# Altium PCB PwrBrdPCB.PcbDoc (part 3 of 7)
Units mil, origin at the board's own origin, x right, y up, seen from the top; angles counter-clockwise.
Board outline 8000 x 5500 mil, 4 copper layers (Top Layer, Internal 1, Internal 2, Bottom Layer), stack 61.834 mil thick; 682 components, 380 nets, 1899 pads, 766 vias.
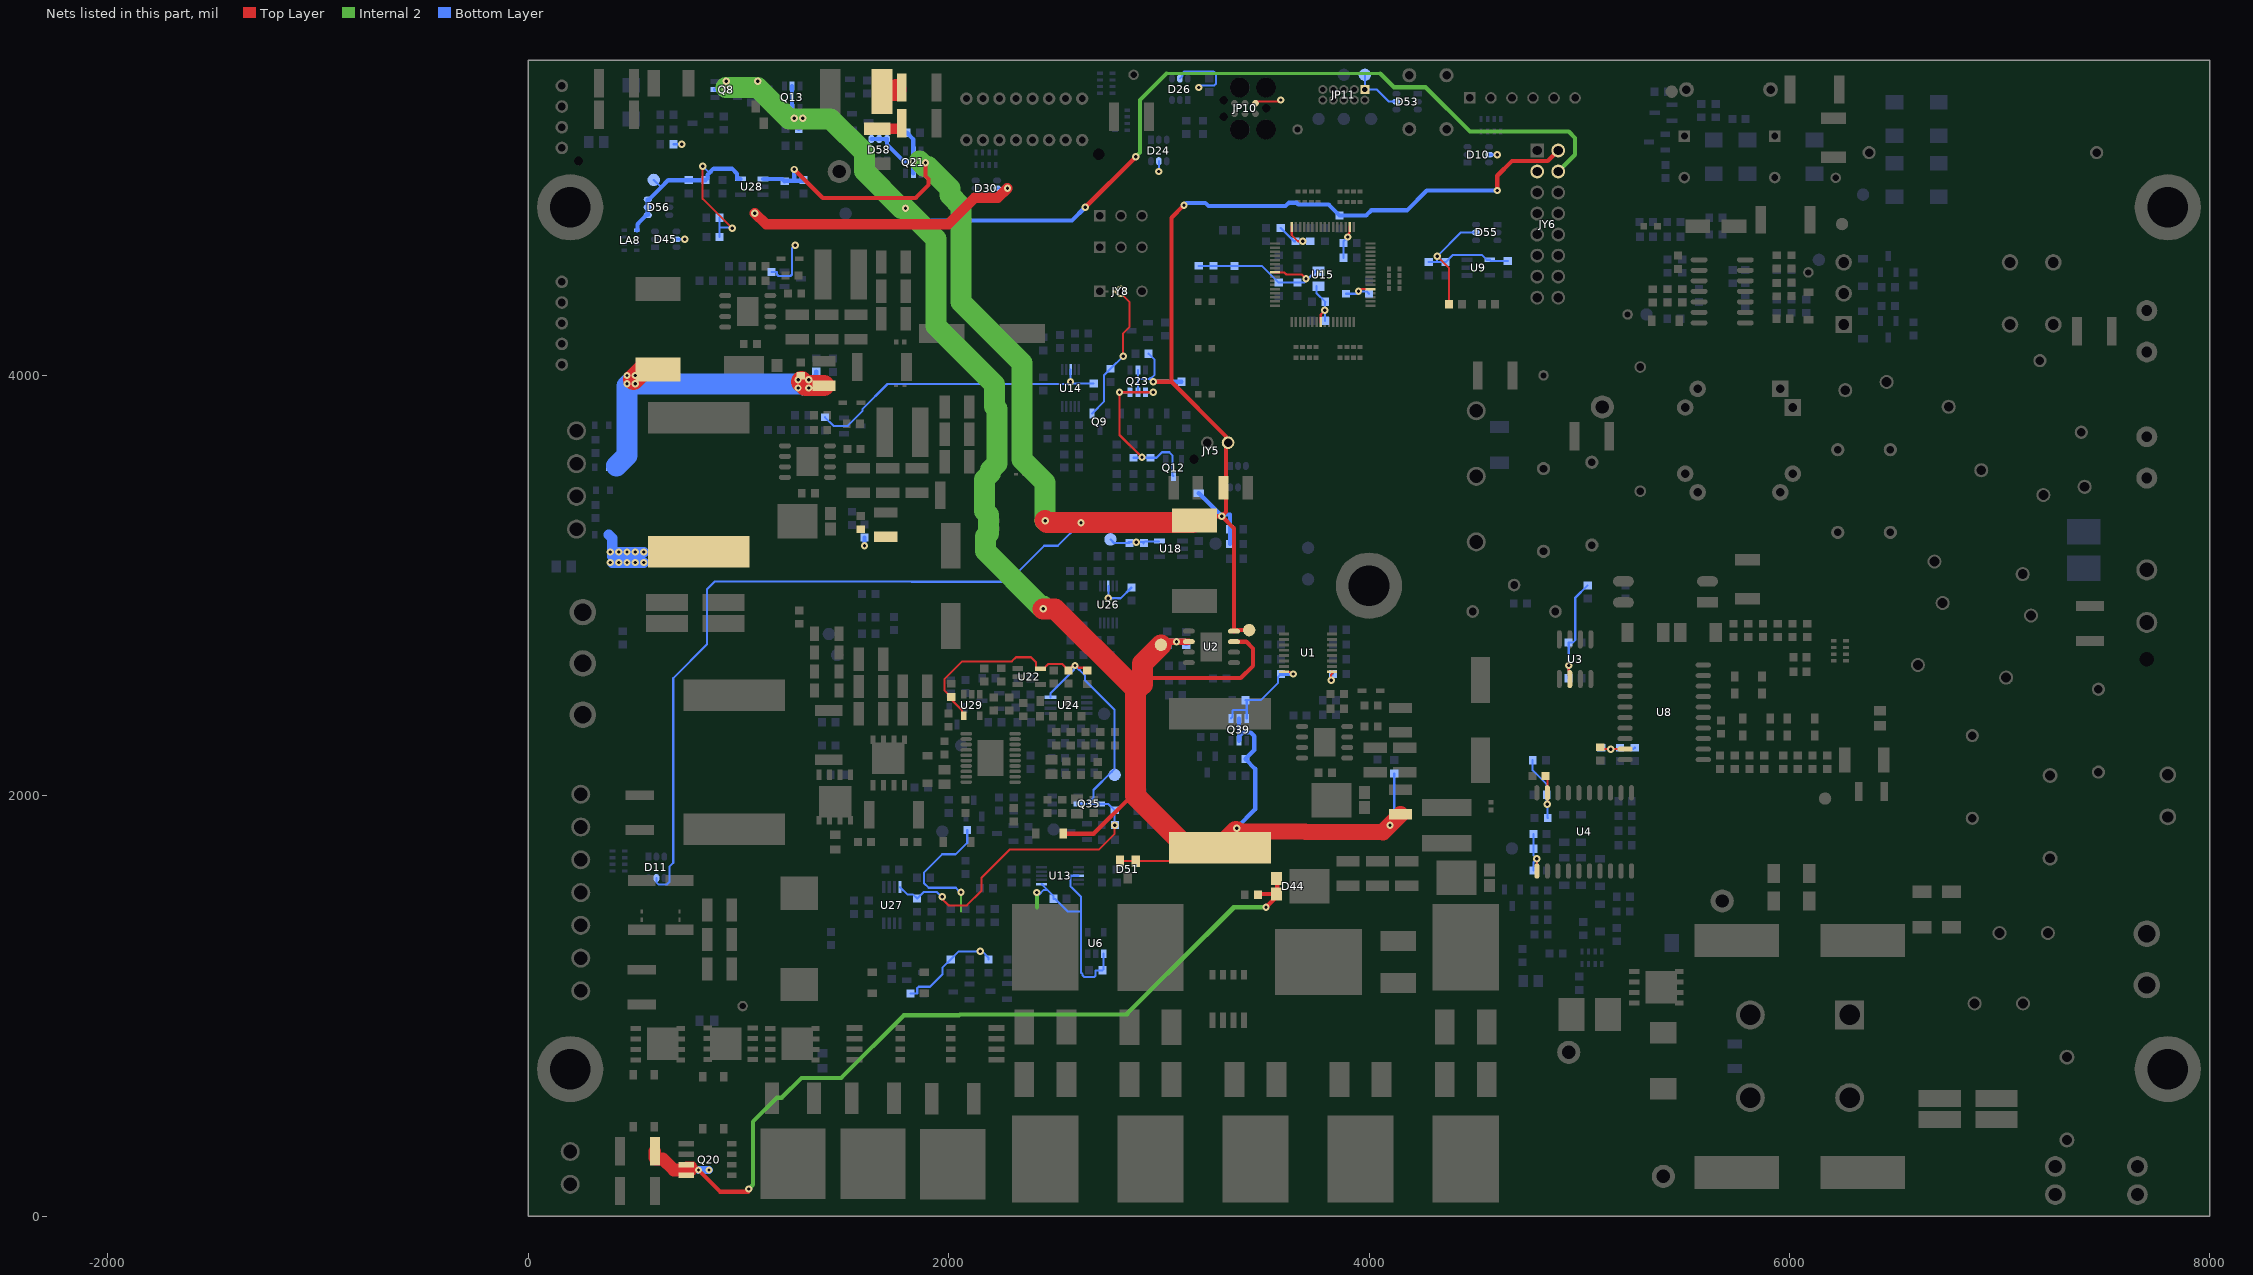
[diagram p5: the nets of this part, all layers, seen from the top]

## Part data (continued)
D4 D5 D6 D7 D19 D20 D21 D22 D27 D28 D32 D33 D34 D35 D36 D37 D47: library part DIO-00004, "Diode Standard 100V 150mA Surface Mount SOD-123", manufacturer="Micro Commercial Co", manufacturer_pn=1N4148W-TP, Supplier Part Number 1=1N4148WTPMSCT-ND
D8: library part DIO-00038, "TVS DIODE 26VWM 42.1VC SMD", manufacturer="Bourns Inc.", manufacturer_pn=5.0SMDJ26CA-H, Supplier Part Number 1=5.0SMDJ26CA-HCT-ND
D10 D24 D26 D30 D45 D53 D55 D56: library part DIO-00013, "TVS DIODE 3.3VWM 6VC SOT26", manufacturer="Diodes Incorporated", manufacturer_pn=D5V0P4UR6SO-7, Supplier Part Number 1=D5V0P4UR6SO-7DICT-ND
D11 D52 D58: library part DIO-00000, "TVS DIODE 6TSOP", manufacturer="Nexperia USA Inc.", manufacturer_pn=PRTR5V0U4D,125, Supplier Part Number 1=1727-3890-1-ND
D12 D41 D42 D43 D44: library part DIO-00037, "Diode Schottky 60V 20A Surface Mount TO-277A (SMPC)", manufacturer="Taiwan Semiconductor Corporation", manufacturer_pn="TSP20U60S S1G", Supplier Part Number 1="TSP20U60S S1GCT-ND"
D13: library part DIO-00010, "Zener Diode 10V 1W ±5% Surface Mount SMA", manufacturer="Diodes Incorporated", manufacturer_pn=SMAZ10-13-F, Supplier Part Number 1=SMAZ10-FDICT-ND
D14 D15 D25 D38 D39: library part DIO-00009, "Diode Standard 1000V (1kV) 1A Surface Mount SMA (DO-214AC)", manufacturer="Fairchild Semiconductor", manufacturer_pn=S1M, Supplier Part Number 1=S1MFSCT-ND
D16 D40: library part DIO-00017, "Zener Diode 8.2V 1W ±5% Surface Mount SMA", manufacturer="Diodes Incorporated", manufacturer_pn=SMAZ8V2-13-F, Supplier Part Number 1=SMAZ8V2-FDICT-ND
D17: library part DIO-00011, "Diode Standard 4000V (4kV) 250mA Through Hole DO-204AL (DO-41)", manufacturer="Vishay Semiconductor Diodes Division", manufacturer_pn=GP02-40-E3/54, Supplier Part Number 1=GP02-40-E3/54GICT-ND
D23 D49 D50: library part DIO-00042, "Zener Diode 5.6V 200mW ±2% Surface Mount SOD-323F", manufacturer="ON Semiconductor", manufacturer_pn=MM3Z5V6B, Supplier Part Number 1=MM3Z5V6BCT-ND
D29: library part DIO-00018, "TVS DIODE 24VWM 38.9VC SMA", manufacturer="Diodes Incorporated", manufacturer_pn=SMAJ24A-13-F, Supplier Part Number 1=SMAJ24A-FDICT-ND
D31: library part LED-00007, "Green 571nm LED Indication - Discrete 2V 0603 (1608 Metric) 35mcd clear", manufacturer="Lite-On Inc.", manufacturer_pn=LTST-C191KGKT, Supplier Part Number 1=160-1446-1-ND
D48: library part DIO-00030, "Diode Schottky 80V 500mA Surface Mount SOD-123", manufacturer="Diodes Incorporated", manufacturer_pn=MBR0580S1-7, Supplier Part Number 1=MBR0580S1-7DICT-ND
D51 D57: library part DIO-00043, "21V Clamp 1.9A Ipp Tvs Diode Surface Mount SOT-23-3 (TO-236)", manufacturer="ON Semiconductor", manufacturer_pn=MMBZ15VALT1G, Supplier Part Number 1=MMBZ15VALT1GOSCT-ND
F3: library part FUSE-00010, "Polymeric PTC Resettable Fuse 15V 3A Ih Surface Mount 2920 (7351 Metric), Concave", manufacturer="Littelfuse Inc.", manufacturer_pn=2920L300/15DR, Supplier Part Number 1=F2875CT-ND
F4 F5: library part FUSE-00016, "Polymeric PTC Resettable Fuse 16V 1.1A Ih Surface Mount 1812 (4532 Metric), Concave", manufacturer="Bel Fuse Inc.", manufacturer_pn=0ZCG0110AF2C, Supplier Part Number 1=507-1767-1-ND
FC1: library part CONN-00117, "FUSE HOLDER BLADE 500V 20A PCB", manufacturer="Keystone Electronics", manufacturer_pn=3568, Supplier Part Number 1=36-3568-ND
FC3 FC4: library part CONN-00079, "Fuse Clip 10A 1 Circuit Cartridge PCB 5x20mm", manufacturer="Schurter Inc.", manufacturer_pn=0751.0110, Supplier Part Number 1=486-2019-ND
GDT1 GDT2: library part PROT-00004, "GDT 75V 10KA THROUGH HOLE", manufacturer="Littelfuse Inc.", manufacturer_pn=SL1411A075A, Supplier Part Number 1=F5590CT-ND, value_text=75
GDT3: library part PROT-00002, "Gas Discharge Tube 1500V 5000A (5kA) 2 Pole Through Hole", manufacturer="Littelfuse Inc.", manufacturer_pn=CG31.5L, Supplier Part Number 1=F2760-ND, value_text=1500
GDT4 GDT5: library part PROT-00003, "Gas Discharge Tube 2500V 5000A (5kA) 2 Pole Through Hole", manufacturer="Littelfuse Inc.", manufacturer_pn=CG32.5L, Supplier Part Number 1=F2745-ND, value_text=2500
JP1: library part CONN-00118, "2 Positions Header Connector 0.244\" (6.20mm) Through Hole Tin", manufacturer="JST Sales America Inc.", manufacturer_pn=B02P-VL, Supplier Part Number 1=455-2361-ND
JP2: library part CONN-00071, "0.250\" (6.35mm) Quick Connect Male Solder Connector Non-Insulated", manufacturer="TE Connectivity AMP Connectors", manufacturer_pn=63849-1, Supplier Part Number 1=63849-1-ND
JP3: library part CONN-00069, "5 Positions Header, Unshrouded Connector 0.312\" (7.92mm) Through Hole Tin", manufacturer="TE Connectivity AMP Connectors", manufacturer_pn=1-1123724-3, Supplier Part Number 1=A106609-ND
JP4: library part CONN-00078, "2 Positions Header, Shrouded Connector 0.250\" (6.35mm) Through Hole Tin, MLX series", manufacturer="Molex, LLC", manufacturer_pn=0432550059, Supplier Part Number 1=WM4055-ND
JP5: library part CONN-00119, "3 Positions Header Connector 0.244\" (6.20mm) Through Hole Tin", manufacturer="JST Sales America Inc.", manufacturer_pn=B03P-VL, Supplier Part Number 1=455-2362-ND
JP6: library part CONN-00087, "7 Positions Header, Unshrouded Connector 0.156\" (3.96mm) Through Hole Tin", manufacturer="TE Connectivity AMP Connectors", manufacturer_pn=3-1123723-7, Supplier Part Number 1=A117563-ND
JP7: library part CONN-00064, "4 Positions Header, Shrouded Connector 0.098\" (2.50mm) Through Hole Tin", manufacturer="JST Sales America Inc.", manufacturer_pn=B4B-XH-AM(LF)(SN), Supplier Part Number 1=455-2237-ND
JP8: library part CONN-00067, "2 Positions Header, Unshrouded Connector 0.156\" (3.96mm) Through Hole Tin (blue)", manufacturer="TE Connectivity AMP Connectors", manufacturer_pn=3-1123723-2, Supplier Part Number 1=A117558-ND
JP9: library part CONN-00065, "16 Positions Header, Shrouded Connector 0.079\" (2.00mm) Through Hole Tin", manufacturer="Molex, LLC", manufacturer_pn=0559171610, Supplier Part Number 1=WM9819-ND
JP10: library part NOBOM-00009, "Tag Connect TC2030 LEGS", manufacturer="New Horizons"
JP11: library part CONN-00023, "10 Positions Header, Shrouded Connector 0.050\" (1.27mm) Through Hole Gold", manufacturer="CNC Tech", manufacturer_pn=3220-10-0100-00, Supplier Part Number 1=1175-1627-ND
JP12: library part CONN-00034, "6 Positions Header, Unshrouded Connector 0.100\" (2.54mm) Through Hole Gold", manufacturer=3M, manufacturer_pn=961106-6404-AR, Supplier Part Number 1=3M9451-ND
JP13: library part CONN-00068, "4 Positions Header, Unshrouded Connector 0.156\" (3.96mm) Through Hole Tin (GRN)", manufacturer="TE Connectivity AMP Connectors", manufacturer_pn=6-1123723-4, Supplier Part Number 1=A116707-ND
JP14: library part CONN-00116, "5 Positions Header Connector 0.098\" (2.50mm) Through Hole Tin", manufacturer="JST Sales America Inc.", manufacturer_pn=B5B-XH-A(LF)(SN), Supplier Part Number 1=455-2270-ND
JY1 JY2 JY8: library part CONN-00030, "3 Positions Header, Unshrouded Connector 0.100\" (2.54mm) Through Hole Gold", manufacturer=3M, manufacturer_pn=961103-6404-AR, Supplier Part Number 1=3M9448-ND
JY5: library part CONN-00072, "2 Positions Header, Shrouded Connector 0.098\" (2.50mm) Through Hole Tin", manufacturer="JST Sales America Inc.", manufacturer_pn=B2B-XH-AM(LF)(SN), Supplier Part Number 1=455-2273-ND
JY6: library part CONN-00121, "16 Positions Header, Unshrouded, Breakaway Connector 0.100\" (2.54mm) Through Hole Gold", manufacturer="Sullins Connector Solutions", manufacturer_pn=PRPC008DAAN-RC, Supplier Part Number 1=S2011EC-08-ND
K1: library part RELAY-00002, "General Purpose Relay SPST Latching 2 coil 12V 20A RTS3LF12", manufacturer="TE Connectivity relay divisions", manufacturer_pn=2-1415898-5, Supplier Part Number 1=655-2-1415898-5
L1: library part IND-00021, "560µH @ 10kHz 2 Line Common Mode Choke Through Hole 20A DCR 2.8 mOhm", manufacturer="Wurth Electronics Inc", manufacturer_pn=S14100038, Supplier Part Number 1=732-7139-ND, value_text=0.56m
L2: library part IND-00024, "2.2uH Shielded Wirewound Inductor 22A 4.2 mOhm Max Nonstandard", manufacturer="Bourns Inc.", manufacturer_pn=SRP1270-2R2M, Supplier Part Number 1=SRP1270-2R2MCT-ND, value_text=2.2u
L3: library part IND-00025, "10uH Shielded Molded Inductor 19A 9.33 mOhm Max Nonstandard", manufacturer="Vishay Dale", manufacturer_pn=IHLP6767GZER100M11, Supplier Part Number 1=541-1286-1-ND, value_text=10u
L4 L13: library part FER-00010, "2 Line Common Mode Choke Surface Mount 170 Ohm @ 100MHz 20A DCR 1 mOhm", manufacturer="Laird Technologies EMI", manufacturer_pn=CM3440Z171R-10, Supplier Part Number 1=240-2463-1-ND, value_text=170
L5 L8 L11 L12 L35: library part FER-00005, "FERRITE BEAD 1 KOHM 0805 1LN 0.28 ohm", manufacturer="Murata Electronics North America", manufacturer_pn=BLM21AG102SN1D, Supplier Part Number 1=490-1041-1-ND, value_text=1k
L6 L39: library part IND-00013, "33µH Shielded Molded Inductor 10.7A 37 mOhm Max Nonstandard", manufacturer="Vishay Dale", manufacturer_pn=IHLP6767GZER330M11, Supplier Part Number 1=541-1289-1-ND, value_text=33u
L7 L14 L15 L17 L19 L20 L27 L28 L33: library part FER-00006, "FERRITE BEAD 785 OHM 1812 1LN 50mohm", manufacturer="Wurth Electronics Inc", manufacturer_pn=742792515, Supplier Part Number 1=732-1642-1-ND, value_text=785
L9 L42: library part IND-00008, "10µH Shielded Wirewound Inductor 6A 19.5 mOhm Max Nonstandard", manufacturer="Bourns Inc.", manufacturer_pn=SRR1280-100M, Supplier Part Number 1=SRR1280-100MCT-ND, value_text=10u
L10: library part IND-00022, "2 Line Common Mode Choke Surface Mount 20A DCR 4.1 mOhm", manufacturer="Pulse Electronics Corporation", manufacturer_pn=PG1265NL, Supplier Part Number 1=553-3913-5-ND, value_text=0.38m
L16 L45 L46: library part IND-00023, "2.2µH Semi-Shielded Wirewound Inductor 6A 15 mOhm Nonstandard", manufacturer="Bourns Inc.", manufacturer_pn=SRN6045TA-2R2Y, Supplier Part Number 1=SRN6045TA-2R2YCT-ND, value_text=2.2u
L18: library part IND-00019, "3.3mH @ 10kHz 2 Line Common Mode Choke Through Hole 2.2A DCR 110 mOhm", manufacturer="EPCOS (TDK)", manufacturer_pn=B82732R2222B030, Supplier Part Number 1=495-2779-ND, value_text=3.3m
L34: library part IND-00020, "3mH @ 100kHz 2 Line Common Mode Choke Through Hole 2A DCR 100 mOhm", manufacturer=Kemet, manufacturer_pn=SC-02-30GJ, Supplier Part Number 1=399-10641-ND, value_text=3m
L40 L41 L43 L44: library part FER-00008, "FERRITE BEAD 26 OHM 0603 1LN 7 mohm", manufacturer="TDK Corporation", manufacturer_pn=MPZ1608S260ATAH0, Supplier Part Number 1=445-172749-1-ND, value_text=26
L47 L48 L49 L50: library part FER-00011, "FERRITE BEAD 100 OHM 1812 1LN 10mohm", manufacturer="Laird Technologies EMI", manufacturer_pn=HI1812V101R-10, Supplier Part Number 1=240-2543-1-ND, value_text=100
LA1 LA2 LA3 LA4 LA5 LA6 LA7 LA8: library part FER-00009, "FERRITE BEAD 600 OHM 1206 4LN", manufacturer="Taiyo Yuden", manufacturer_pn=BK32164S601-T, Supplier Part Number 1=587-2698-1-ND, value_text=600
MECH1 MECH3 MECH4: library part MECH-00014, "2 (1 x 2) Position Shunt Connector Black Open Top 0.100\" (2.54mm) Gold", manufacturer="Sullins Connector Solutions", manufacturer_pn=QPC02SXGN-RC, Supplier Part Number 1=S9337-ND
MECH2 MECH5 MECH6: library part MECH-00031, "Heat Sink Aluminum Nitride Ceramic Heat Spreader Q-Bridge", manufacturer="American Technical Ceramics", manufacturer_pn=QB0805A40WYTD, Supplier Part Number 1=1284-1835-1-ND
NT1: library part NOBOM-00005, "Net tie 0603", manufacturer="New Horizons"
NT2 NT3 NT4 NT5 NT6: library part NOBOM-00016, "Net tie 0.254mm no pads", manufacturer="New Horizons"
Q1 Q2 Q3 Q20: library part FET-00017, "Mosfet Array 2 N-Channel (Dual) 60V 30A 53W Surface Mount LFPAK56D", manufacturer="Nexperia USA Inc.", manufacturer_pn=BUK7K17-60EX, Supplier Part Number 1=1727-1481-1-ND
Q4 Q26 Q27 Q28 Q30 Q32: library part FET-00018, "N-Channel 60V 29A (Ta), 108A (Tc) 3.2W (Ta), 125W (Tc) Surface Mount Dual Cool™56", manufacturer="ON Semiconductor", manufacturer_pn=FDMS86500DC, Supplier Part Number 1=FDMS86500DCFSCT-ND
Q5 Q6 Q12 Q15: library part BJT-00001, "Bipolar (BJT) Transistor NPN 60V 500mA 350mW Surface Mount SOT-23-3", manufacturer="ON Semiconductor", manufacturer_pn=BCV72, Supplier Part Number 1=BCV72CT-ND
Q7 Q9 Q10 Q11 Q14 Q16 Q17 Q18 Q19 Q22 Q24 Q25 Q29 Q31 Q34 Q36 Q38 Q40: library part FET-00002, "MOSFET N-CH 30V 3.4A SOT23", manufacturer="Infineon Technologies", manufacturer_pn=IRLML6346TRPBF, Supplier Part Number 1=IRLML6346TRPBFCT-ND
Q8 Q13 Q21 Q23 Q33 Q35 Q39: library part FET-00023, "Mosfet Array 2 P-Channel (Dual) 30V 2A 500mW Surface Mount PG-TSOP-6-6", manufacturer="Infineon Technologies", manufacturer_pn=BSL308PEH6327XTSA1, Supplier Part Number 1=BSL308PEH6327XTSA1CT-ND
Q37: library part BJT-00002, "TRANS PNP 60V 0.6A SOT23", manufacturer="ON Semiconductor", manufacturer_pn=MMBT2907ALT1G, Supplier Part Number 1=MMBT2907ALT1GOSCT-ND
R1 R7 R32 R36 R43 R45 R47 R62 R63 R80 R81 R82 R83 R84 R86 R114 R122 R123 R139 R142 R145 R146 R149 R150 R164 R181 R184 R185 R186 R193 R194 R195 R196: library part RES-00112, "100 kOhms ±1% 0.1W, 1/10W Chip Resistor 0603 (1608 Metric) Automotive AEC-Q200 Thick Film", manufacturer="Panasonic Electronic Components", manufacturer_pn=ERJ-3EKF1003V, Supplier Part Number 1=P100KHCT-ND, value_text=100k
R2 R27 R28: library part RES-00083, "RES SMD 33 OHM 1% 25W DPAK", manufacturer="Bourns Inc.", manufacturer_pn=PWR163S-25-33R0F, Supplier Part Number 1=PWR163S-25-33R0F-ND, value_text=33
R3 R49 R70 R102 R153 R154 R157: library part RES-00019, "RES SMD 200 OHM 1% 1/10W 0603", manufacturer="Panasonic Electronic Components", manufacturer_pn=ERJ-3EKF2000V, Supplier Part Number 1=P200HCT-ND, value_text=200
R4 R9 R17 R37 R39 R40 R46 R58 R64 R73 R87 R89 R90 R115 R124 R152 R167 R177 R189: library part RES-00107, "10 kOhms ±1% 0.1W, 1/10W Chip Resistor 0603 (1608 Metric) Automotive AEC-Q200 Thick Film", manufacturer="Panasonic Electronic Components", manufacturer_pn=ERJ-3EKF1002V, Supplier Part Number 1=P10.0KHCT-ND, value_text=10k
R5 R6 R20 R21 R22 R30 R31 R33 R35 R51 R72 R76 R78 R98 R155 R156 R158 R174 R179 R212: library part RES-00013, "RES SMD 4.75K OHM 1% 1/10W 0603", manufacturer="Panasonic Electronic Components", manufacturer_pn=ERJ-3EKF4751V, Supplier Part Number 1=P4.75KHCT-ND, value_text=4.75k
R8 R53 R55 R56 R65 R71 R93 R95: library part RES-00114, "1 MOhms ±1% 0.1W, 1/10W Chip Resistor 0603 (1608 Metric) Automotive AEC-Q200 Thick Film", manufacturer="Panasonic Electronic Components", manufacturer_pn=ERJ-3EKF1004V, Supplier Part Number 1=P1.00MHCT-ND, value_text=1M
R10 R11 R12 R13 R14 R18 R19 R26 R29: library part RES-00082, "RES SMD 8 OHM 1% 35W D2PAK", manufacturer="Bourns Inc.", manufacturer_pn=PWR263S-35-8R00F, Supplier Part Number 1=PWR263S-35-8R00F-ND, value_text=8
R15 R16 R23 R24 R34: library part RES-00067, "RES SMD 1KOHM 0.1% 1/10W 0603", manufacturer="Panasonic Electronic Components", manufacturer_pn=ERA-3AEB102V, Supplier Part Number 1=P1.0KDBCT-ND, value_text=1k
R25 R77: library part RES-00044, "RES SMD 0.001 OHM 1% 3W 2512", manufacturer="Bourns Inc.", manufacturer_pn=CRE2512-FZ-R001E-3, Supplier Part Number 1=CRE2512-FZ-R001E-3CT-ND, value_text=0.001
R38: library part RES-00027, "RES SMD 33.2K OHM 1% 1/10W 0603", manufacturer="Panasonic Electronic Components", manufacturer_pn=ERJ-3EKF3322V, Supplier Part Number 1=P33.2KHCT-ND, value_text=33.2k
R41 R48 R111 R116 R119 R148: library part RES-00064, "RES SMD 332K OHM 1% 1/10W 0603", manufacturer="Panasonic Electronic Components", manufacturer_pn=ERJ-3EKF3323V, Supplier Part Number 1=P332KHCT-ND, value_text=332k
R42 R50 R117 R126: library part RES-00063, "RES SMD 140K OHM 1% 1/10W 0603", manufacturer="Panasonic Electronic Components", manufacturer_pn=ERJ-3EKF1403V, Supplier Part Number 1=P140KHCT-ND, value_text=140k
R44 R113 R121: library part RES-00062, "RES SMD 13.0K OHM 1% 1/10W 0603", manufacturer="Panasonic Electronic Components", manufacturer_pn=ERJ-3EKF1302V, Supplier Part Number 1=P13.0KHCT-ND, value_text=13k
R52 R74 R100 R101 R103 R104 R109 R110 R128 R129 R130 R131 R132 R133 R134 R135 R143 R144 R147 R151 R183 R187 R188 R190 R197 R198 R199 R201 R203 R208 R210: library part RES-00113, "1 kOhms ±1% 0.1W, 1/10W Chip Resistor 0603 (1608 Metric) Automotive AEC-Q200 Thick Film", manufacturer="Panasonic Electronic Components", manufacturer_pn=ERJ-3EKF1001V, Supplier Part Number 1=P1.00KHCT-ND, value_text=1k
R54 R66 R67 R106 R108 R176 R200 R204 R205 R206 R207 R209 R211 R213 R214: library part RES-00051, "RES SMD 27.4KOHM 0.1% 1/10W 0603", manufacturer="Panasonic Electronic Components", manufacturer_pn=ERA-3AEB2742V, Supplier Part Number 1=P27.4KDBCT-ND, value_text=27.4k
R57: library part RES-00057, "17.4k Ohm ±0.1% 0.1W, 1/10W Chip Resistor 0603 (1608 Metric) Moisture Resistant Thin Film", manufacturer=Yageo, manufacturer_pn=RT0603BRD0717K4L, Supplier Part Number 1=YAG1547CT-ND, value_text=17.4k
R59 R61 R68 R94 R141: library part RES-00032, "RES SMD 475K OHM 1% 1/10W 0603", manufacturer="Panasonic Electronic Components", manufacturer_pn=ERJ-3EKF4753V, Supplier Part Number 1=P475KHCT-ND, value_text=475k
R60: library part RES-00066, "RES SMD 127KOHM 0.1% 1/10W 0603", manufacturer="Panasonic Electronic Components", manufacturer_pn=ERA-3AEB1273V, Supplier Part Number 1=P127KDBCT-ND, value_text=127k
R69 R180: library part RES-00056, "3.4k Ohm ±0.1% 0.1W, 1/10W Chip Resistor 0603 (1608 Metric) Moisture Resistant Thin Film", manufacturer=Yageo, manufacturer_pn=RT0603BRD073K4L, Supplier Part Number 1=YAG1653CT-ND, value_text=3.4k
R75 R79: library part RES-00035, "RES SMD 511 OHM 1% 1/10W 0603", manufacturer="Panasonic Electronic Components", manufacturer_pn=ERJ-3EKF5110V, Supplier Part Number 1=P511HCT-ND, value_text=511
R85: library part RES-00128, "220 kOhms ±1% 0.5W, 1/2W Chip Resistor 2010 (5025 Metric) High Voltage Thick Film", manufacturer="Bourns Inc.", manufacturer_pn=CHV2010-FX-2203ELF, Supplier Part Number 1=CHV2010-FX-2203ELFCT-ND, value_text=220k
R88 R120: library part RES-00031, "RES SMD 52.3K OHM 1% 1/10W 0603", manufacturer="Panasonic Electronic Components", manufacturer_pn=ERJ-3EKF5232V, Supplier Part Number 1=P52.3KHCT-ND, value_text=52.3k
R91 R99: library part RES-00125, "3.3 MOhms ±1% 0.5W, 1/2W Chip Resistor 2010 (5025 Metric) High Voltage Thick Film", manufacturer="Bourns Inc.", manufacturer_pn=CHV2010-FX-3304ELF, Supplier Part Number 1=CHV2010-FX-3304ELFCT-ND, value_text=3.3M
R92: library part RES-00150, "1 MOhms ±1% 1W Chip Resistor Nonstandard High Voltage Thick Film", manufacturer="Bourns Inc.", manufacturer_pn=CHV2512-FX-1004ELF, Supplier Part Number 1=CHV2512-FX-1004ELFCT-ND, value_text=1M
R96: library part RES-00026, "RES SMD 30.1K OHM 1% 1/10W 0603", manufacturer="Vishay Dale", manufacturer_pn=CRCW060330K1FKEA, Supplier Part Number 1=541-30.1KHCT-ND, value_text=30.1k
R97 R166 R191: library part RES-00055, "RES SMD 2.74K OHM 1% 1/10W 0603", manufacturer="Panasonic Electronic Components", manufacturer_pn=ERJ-3EKF2741V, Supplier Part Number 1=P2.74KHCT-ND, value_text=2.74k
R105 R169: library part RES-00098, "RES SMD 100 OHM 5% 1W 2512", manufacturer="Panasonic Electronic Components", manufacturer_pn=ERJ-1TYJ101U, Supplier Part Number 1=PT100XCT-ND, value_text=100
R107 R192: library part RES-00050, "RES SMD 4.22KOHM 0.1% 1/10W 0603", manufacturer=Yageo, manufacturer_pn=RT0603BRD074K22L, Supplier Part Number 1=YAG1674CT-ND, value_text=4.22k
R112: library part RES-00154, "162 kOhms ±1% 0.1W, 1/10W Chip Resistor 0603 (1608 Metric) Automotive AEC-Q200 Thick Film", manufacturer="Panasonic Electronic Components", manufacturer_pn=ERJ-3EKF1623V, Supplier Part Number 1=P162KHCT-ND, value_text=162k
R118 R127: library part RES-00045, "RES SMD 0.025 OHM 1% 3W 2512", manufacturer="Bourns Inc.", manufacturer_pn=CRA2512-FZ-R025ELF, Supplier Part Number 1=CRA2512-FZ-R025ELFCT-ND, value_text=0.025
R125: library part RES-00096, "RES SMD 274K OHM 1% 1/10W 0603", manufacturer="Panasonic Electronic Components", manufacturer_pn=ERJ-3EKF2743V, Supplier Part Number 1=P274KHCT-ND, value_text=274k
R136 R137 R138: library part RES-00097, "RES SMD 0.1 OHM 1% 1/6W 0402", manufacturer="Panasonic Electronic Components", manufacturer_pn=ERJ-2BSFR10X, Supplier Part Number 1=P.10AKCT-ND, value_text=0.1
R140 R160: library part RES-00036, "RES SMD 0.01 OHM 1% 3W 2512", manufacturer="Bourns Inc.", manufacturer_pn=CRA2512-FZ-R010ELF, Supplier Part Number 1=CRA2512-FZ-R010ELFCT-ND, value_text=0.01
R159 R162: library part RES-00100, "10 Ohm ±5% 0.25W, 1/4W Chip Resistor 0603 (1608 Metric) Automotive AEC-Q200, Pulse Withstanding Thick Film", manufacturer="Rohm Semiconductor", manufacturer_pn=ESR03EZPF10R0, Supplier Part Number 1=RHM10.0ADCT-ND, value_text=10
R161 R173: library part RES-00010, "RES SMD 0.0OHM JUMPER 1/10W 0603", manufacturer="Panasonic Electronic Components", manufacturer_pn=ERJ-3GEY0R00V, Supplier Part Number 1=P0.0GCT-ND, value_text=0
R163 R165: library part RES-00126, "RES SMD 4.75 OHM 1% 1/10W 0603", manufacturer="Vishay Dale", manufacturer_pn=CRCW06034R75FKEA, Supplier Part Number 1=541-4.75HHCT-ND, value_text=4.75
R168: library part RES-00101, "38.3k Ohm ±1% 0.1W, 1/10W Chip Resistor 0603 (1608 Metric) Automotive AEC-Q200 Thick Film", manufacturer="Panasonic Electronic Components", manufacturer_pn=ERJ-3EKF3832V, Supplier Part Number 1=P38.3KHCT-ND, value_text=38.3k
R170: library part RES-00102, "301k Ohm ±1% 0.1W, 1/10W Chip Resistor 0603 (1608 Metric) Automotive AEC-Q200 Thick Film", manufacturer="Panasonic Electronic Components", manufacturer_pn=ERJ-3EKF3013V, Supplier Part Number 1=P301KHCT-ND, value_text=301k
R171 R175: library part RES-00015, "RES SMD 47.5 OHM 1% 1/10W 0603", manufacturer="Panasonic Electronic Components", manufacturer_pn=ERJ-3EKF47R5V, Supplier Part Number 1=P47.5HCT-ND, value_text=47.5
R172: library part RES-00105, "0.003 Ohm ±1% 3W Chip Resistor 2512 (6432 Metric) Automotive AEC-Q200, Current Sense, Moisture Resistant Metal Element", manufacturer="Bourns Inc.", manufacturer_pn=CRE2512-FZ-R003E-3, Supplier Part Number 1=CRE2512-FZ-R003E-3CT-ND, value_text=0.003
R178 R202: library part RES-00104, "620 Ohm ±0.1% 0.1W, 1/10W Chip Resistor 0603 (1608 Metric) Automotive AEC-Q200 Thin Film", manufacturer="Panasonic Electronic Components", manufacturer_pn=ERA-3AEB621V, Supplier Part Number 1=P620DBCT-ND, value_text=620
R182: library part RES-00103, "1.91k Ohm ±0.1% 0.1W, 1/10W Chip Resistor 0603 (1608 Metric) Automotive AEC-Q200 Thin Film", manufacturer="Panasonic Electronic Components", manufacturer_pn=ERA-3AEB1911V, Supplier Part Number 1=P1.91KDBCT-ND, value_text=1.91k
R215: library part RES-00127, "4.7 MOhms ±1% 0.333W, 1/3W Chip Resistor 1210 (3225 Metric) Automotive AEC-Q200, High Voltage Thick Film", manufacturer="Rohm Semiconductor", manufacturer_pn=KTR25JZPF4704, Supplier Part Number 1=RHM1152CT-ND, value_text=4.7M
RA1 RA2 RA3 RA4 RA5: library part RES-00041, "RES ARRAY 4 RES 22 OHM 1206", manufacturer="CTS Resistor Products", manufacturer_pn=742C083220JP, Supplier Part Number 1=742C083220JPCT-ND, value_text=22
RV1 RV2: library part PROT-00005, "VARISTOR 18V 8KA DISC 20MM", manufacturer="Littelfuse Inc.", manufacturer_pn=V20E11P, Supplier Part Number 1=F6225-ND, value_text=11
RV3: library part PROT-00001, "VARISTOR 470V 10KA DISC 20MM", manufacturer="Littelfuse Inc.", manufacturer_pn=TMOV20RP300M, Supplier Part Number 1=F4045-ND, value_text=300
RV4 RV5 RV6: library part PROT-00000, "VARISTOR 680V 10KA DISC 20MM", manufacturer="Littelfuse Inc.", manufacturer_pn=TMOV20RP420M, Supplier Part Number 1=F4051-ND, value_text=420
SW1: library part SW-00004, "Tactile Switch SPST-NO Top Actuated Through Hole", manufacturer="TE Connectivity ALCOSWITCH Switches", manufacturer_pn=1825910-2, Supplier Part Number 1=450-1649-ND
TP1 TP2 TP4 TP5 TP6 TP10 TP12 TP13 TP16 TP17 TP18 TP19 TP22 TP24 TP25 TP26 TP28 TP29 TP31 TP32 TP33 TP34 TP35 TP36 TP37 TP38 TP39: library part NOBOM-00008, "Test point, SMD, 1.5mm dia (0.059\")", manufacturer="New Horizons"
TP3 TP7 TP8 TP9 TP14 TP15 TP27: library part NOBOM-00007, "Test point, TH, 0.78mm (30mil) hole, 1.27mm (50 mil) pad", manufacturer="New Horizons"
TP11 TP20 TP21 TP23 TP30: library part CONN-00028, "TEST POINT PC MULTI PURPOSE BLK", manufacturer="Keystone Electronics", manufacturer_pn=5011, Supplier Part Number 1=36-5011-ND
U1: library part ICXCV-00015, "IC LEVEL SHIFTER HEX 16-TSSOP", manufacturer="ON Semiconductor", manufacturer_pn=MC14504BDTG, Supplier Part Number 1=MC14504BDTGOS-ND
U2: library part ICPWR-00018, "Buck Switching Regulator IC Positive Adjustable 0.8V 1 Output 3A 8-SOIC (0.154in, 3.90mm Width) Exposed Pad", manufacturer="Alpha & Omega Semiconductor Inc.", manufacturer_pn=AOZ3015PI, Supplier Part Number 1=785-1642-1-ND
U3: library part ICDIG-00002, "Real Time Clock (RTC) IC Clock/Calendar I²C, 2-Wire Serial 8-SOIC (0.154in 3.90mm Width)", manufacturer="Maxim Integrated", manufacturer_pn=DS3231MZ/V+, Supplier Part Number 1=DS3231MZ/V+-ND
U4: library part ICANA-00022, "Energy Monitor (Power Meter) 24 bit SPI 20-SOIC", manufacturer="Analog Devices Inc.", manufacturer_pn=ADE7903ARWZ-RL, Supplier Part Number 1=ADE7903ARWZ-RLCT-ND
U5 U10 U12: library part ICPWR-00044, "Buck, Split Rail Switching Regulator IC Positive Adjustable 0.8V 1 Output 5A 8-PowerSOIC (0.154\", 3.90mm Width)", manufacturer="Texas Instruments", manufacturer_pn=TPS54560BQDDARQ1, Supplier Part Number 1=296-45534-1-ND
U6: library part ICANA-00026, "Temperature Sensor Digital, Local -55°C ~ 125°C 11 b SOT-23-5", manufacturer="Microchip Technology", manufacturer_pn=MCP9800A5T-M/OT, Supplier Part Number 1=MCP9800A5T-M/OTCT-ND
U7: library part ICXCV-00005, "Optoisolator Transistor Output 5000Vrms 1 Channel 4-SMD", manufacturer="Lite-On Inc.", Supplier Part Number 1=160-1345-5-ND
U8: library part ICANA-00004, "ADC, Energy Measurement 24 bit SPI 20-SOIC-RI", manufacturer="Analog Devices Inc.", manufacturer_pn=ADE7912ARIZ, Supplier Part Number 1=ADE7912ARIZ-ND
U9: library part ICDIG-00007, "EEPROM Memory IC 16Kb (2K x 8) I²C 900ns SOT-23-5", manufacturer="Microchip Technology", manufacturer_pn=24LC16BT-I/OT, Supplier Part Number 1=24LC16BT-I/OTCT-ND
U11 U25: library part ICPWR-00010, "Shunt Voltage Reference IC 24V ±0.25% 100mA SOT-23-3", manufacturer=STMicroelectronics, manufacturer_pn=TS3431CILT, Supplier Part Number 1=497-4637-1-ND
U13 U14 U26: library part ICANA-00023, "16 Bit Analog to Digital Converter 2, 4 Input 1 Sigma-Delta 10-VSSOP", manufacturer="Texas Instruments", manufacturer_pn=ADS1115IDGSR, Supplier Part Number 1=296-38849-1-ND
U15: library part MCU-00010, "ARM® Cortex®-M0+ SAM D20J Microcontroller IC 32-Bit 48MHz 256KB (256K x 8) FLASH 64-LQFP (10x10)", manufacturer=Atmel, manufacturer_pn=ATSAMD20J18A-AU, Supplier Part Number 1=ATSAMD20J18A-AU-ND
U16 U19 U21: library part ICXCV-00017, "Optoisolator Photovoltaic Output 4500Vrms 1 Channel 4-SOP (2.54mm)", manufacturer="Vishay Semiconductor Opto Division", manufacturer_pn=VOM1271T, Supplier Part Number 1=VOM1271TCT-ND
U17: library part ICANA-00012, "Comparator General Purpose CMOS, MOS, Open-Collector 14-SOIC", manufacturer="Texas Instruments", Supplier Part Number 1=296-26119-1-ND
U18 U22 U28: library part ICPWR-00039, "Linear Voltage Regulator IC Positive Fixed 1 Output 3.3V 200mA SOT-23-5", manufacturer=STMicroelectronics, manufacturer_pn=LDK320AM33R, Supplier Part Number 1=497-16702-1-ND
U23: library part ICPWR-00030, "Buck Regulator Positive Output Step-Down DC-DC Controller IC 20-HTSSOP", manufacturer="Texas Instruments", manufacturer_pn=LM5117PMHX/NOPB, Supplier Part Number 1=296-41310-1-ND
U24 U27: library part ICANA-00025, "Zero-Drift Amplifier 2 Circuit Rail-to-Rail 8-VSSOP", manufacturer="Texas Instruments", manufacturer_pn=OPA2333AIDGKR, Supplier Part Number 1=296-22883-1-ND
U29: library part ICANA-00028, "Series Voltage Reference IC  ±1%  TSOT-23-5", manufacturer="Linear Technology", manufacturer_pn=LT6650IS5#TRMPBF, Supplier Part Number 1=LT6650IS5#TRMPBFCT-ND
Z1 Z2 Z5 Z6 Z9: library part NOBOM-00011, "Mounting hole, 5mm hole, 8mm pad", manufacturer="New Horizons"
Z3 Z4 Z7 Z8 Z14 Z15: "Fiducial, 1mm dia, 3mm solder mask opening", manufacturer="New Horizons"

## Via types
v1: diameter 35, hole 16, Top Layer to Bottom Layer, tented both sides, 409 vias
v2: diameter 35, hole 16, Top Layer to Bottom Layer, 348 vias
v3: diameter 35, hole 16, Top Layer to Bottom Layer, tented bottom, 5 vias
v4: diameter 60, hole 36, Top Layer to Bottom Layer, 2 vias
v5: diameter 65, hole 40.5, Top Layer to Bottom Layer, 2 vias

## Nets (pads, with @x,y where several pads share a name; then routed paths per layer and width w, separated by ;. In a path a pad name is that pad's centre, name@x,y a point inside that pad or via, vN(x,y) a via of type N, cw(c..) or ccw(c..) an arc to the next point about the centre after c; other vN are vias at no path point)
3V3_ANA: C58.1 C59.1 L11.2 U15.8 | length 247
  Top Layer w10: U15.8@3770.16,4253.62 3770.16,4290.16 v1(3790,4310)
  Bottom Layer w10: L11.2@3750,4424.57 3750,4391.49 C59.1@3791.5,4350 3790,4348.5 v1(3790,4310) C58.1@3790,4260
3V3_AUX3: C145.1 C146.1 C183.1 Q35.2 Q35.5 R183.2 R190.1 R204.1 TP31.1 U22.5 U24.8 U27.8 U29.4 | length 3605.6
  Top Layer w10: v1(1970,1520) 1970,1516.85 1965.71,1512.57 1997.78,1480.5 1999.34,1480.5 2000.56,1479.28 2087.12,1479.28 2157.36,1549.52 2157.36,1611.64 2289.72,1744 2714,1744 2790,1820 v1(2790,1860) ; C183.1@2000,2470 2000.98,2470 2064,2406.98 2064,2389.43 U29.4@2072.5,2380.93 ; C183.1@2012.78,2470 2011.8,2470 1980,2501.8 1980,2555.57 2064.43,2640 2301.14,2640 2320.64,2659.5 2392.22,2659.5 2415.99,2635.73 2415.99,2610.81 2424.99,2601.81 2449.57,2601.81 2475.35,2627.59 2539.3,2627.59 C145.1@2570,2596.89 2593.11,2620 v1(2601.56,2620) 2608.32,2620 2618.71,2609.61 2646.3,2609.61 C146.1@2660,2595.91 ; U22.5@2426.15,2604.81 U22.5@2436.99,2604.81
  Bottom Layer w10: U27.8@1768.39,1566.61 1805,1530 1831.5,1530 R204.1@1850,1511.5 1880.7,1542.2 1944.66,1542.2 v1@1970,1516.85 ; v1@1967.43,1514.29 v1@1970,1516.85 ; v1(1970,1520) v1@1970,1516.85 ; U24.8@2484.88,2468.39 2484.88,2488.73 2540,2543.85 2596.77,2600.62 2596.77,2615.22 v1(2601.56,2620) 2649.37,2572.19 2649.37,2548.98 2790,2408.35 2790,2128.28 2775.86,2114.14 2689.5,2027.78 2689.5,1990.99 2660,1961.5 ; Q35.5@2616.85,1961.5 2660,1961.5 ; v1(2790,1860) 2792.99,1860 R190.1@2791.49,1861.5 2790,1862.99 R183.2@2790,1931.5 2760,1961.5 Q35.2@2723.15,1961.5 2660,1961.5
3V3_ISO: C3.1 C5.1 C6.2 C7.1 C8.1 C11.2 C12.2 C18.1 C25.1 C29.1 C50.1 C53.1 C54.1 C55.1 C56.1 C57.1 C65.1 C68.2 C69.2 C73.2 C76.2 C87.1 C88.1 C89.1 C106.1 C111.1 C170.1 D10.5 D24.5 D26.5 D30.5 D45.5 D53.5 D55.5 JP10.1 JP11.1 JY6.3 L11.1 R3.2 R5.2 R6.2 R7.2 R8.2 R17.1 R49.2 R78.2 R81.1 R86.2 R122.2 R141.1 R147.2 R153.2 R154.2 R157.2 R166.2 TP4.1 TP12.1 U1.1 U3.2 U4.1 U4.19 U6.1 U8.19 U9.4 U13.1 U13.8 U14.8 U15.21 U15.34 U15.48 U15.56 U18.5 U26.8 | length 10543.9
  Top Layer w10: JP10.1@3460,5295 3460,5302.25 3572.25,5302.25 v1(3580,5310) ; U15.56@3553.62,4489.84 3597.49,4489.84 3607.31,4480.03 3679.97,4480.03 v1(3700,4460) ; U15.48@3632.36,4706.38 3632.36,4667.64 3661.5,4638.5 v1(3685,4638.5) ; v1(3820,2550) 3820,2577.6 3828.5,2586.1 U1.1@3824.17,2590.43 ; v1(3898.3,4658.26) 3898.3,4669.91 3906.17,4677.79 3906.17,4704.6 U15.34@3907.95,4706.38 ; v1(3950,4400) 3961.1,4411.1 U15.21@4006.38,4411.1 ; v1(4323.86,4567.68) 4380,4511.54 R141.1@4380,4339.03 ; U4.1@4798.5,1642.6 v1(4798.5,1700.16) ; C12.2@4840,2094.64 4848.5,2086.14 U4.19@4848.5,2014.65 v1(4848.5,1960.16) ; v1(4950,2620) 4950,2575 4955,2570 U3.2@4955,2555.51 ; C68.2@5100,2231.5 5109.25,2222.24 v1(5150,2222.24) U8.19@5218.07,2222.24
  Top Layer w50: v1(1078.11,4771.89) 1131.7,4718.3 1998.3,4718.3 2124.5,4844.5 2234.5,4844.5 v1(2280,4890)
  Internal 2 w10: v2(2059.23,1542.2) 2059.23,1450.26 2059.5,1450
  Internal 2 w20: 2420,1470 v1(2420,1540)
  Bottom Layer w10: R78.2@691.5,5100 v1(730,5100) ; D45.5@705.42,4647.8 v1(745.03,4647.8) ; R122.2@1157.13,4491.5 1183.5,4491.5 1183.5,4479.93 1190.53,4472.9 1247.72,4472.9 1254.75,4479.93 1254.75,4604.75 v1(1270,4620) ; R86.2@1411.5,3801.02 1452.52,3760 1520,3760 1590,3830 1590,3840 1709.2,3959.2 2549.2,3959.2 ; R157.2@1818.5,1060 1850.8,1060 1850.8,1084.66 1857.82,1091.68 1911.68,1091.68 1970,1150 1970,1181.5 R154.2@2010,1221.5 2048.5,1260 v1(2150,1260) 2160,1260 2190,1230 R153.2@2190,1221.5 ; v2(2059.23,1542.2) 2054.32,1542.2 2033.8,1562.72 1904.65,1562.72 1882.03,1585.34 1882.03,1634.66 1969.57,1722.2 2033.69,1722.2 2088.5,1777.01 R166.2@2088.5,1837.19 ; D30.5@2230.98,4890 v1(2280,4890) ; v1(2420,1540) 2430,1530 2453.03,1553.03 2470,1553.03 ; U13.1@2442.4,1580.63 2470,1553.03 ; U14.8@2580,4027.6 v1(2580,3970) ; U13.8@2617.6,1620 2580,1620 2579.02,1619.02 2579.02,1569.75 2586.05,1562.72 2587.28,1562.72 2630,1520 2630,1450 ; C111.1@2690,3961.5 2581.5,3961.5 v1@2580,3960 ; U6.1@2737.5,1249 2737.5,1176 C29.1@2731.5,1170 2699.2,1170 2699.2,1145.34 2692.17,1138.31 2644.83,1138.31 2637.8,1145.34 2637.8,1152.2 2630,1160 2630,1450 ; U26.8@2760,2997.6 v1(2760,2940) 2818.51,2940 C170.1@2870,2991.5 ; TP12.1@2770,3220 2787.01,3202.99 C5.1@2860,3202.99 ; C5.1@2856.35,3206.85 v1(2893.15,3206.85) C65.1@2926.34,3206.85 ; C65.1@2926.34,3201.54 2935.75,3210.95 U18.5@3000,3210.95 ; v1(3000,4970) D24.5@3000,5019.02 ; D26.5@3100,5412.08 3111.82,5423.9 3111.82,5436.77 3120,5444.95 3260,5444.95 3262.75,5442.2 3264.66,5442.2 3271.69,5435.17 3271.69,5387.82 3263.86,5380 3200,5380 v1(3190,5370) ; R3.2@3190,4521.5 R49.2@3260,4521.5 3490,4521.5 C50.1@3570,4441.5 C53.1@3660,4441.5 3691.5,4441.5 3745.43,4495.43 L11.1@3750,4495.43 ; R7.2@3580,4701.5 3642.99,4638.5 C89.1@3650,4638.5 ; v1(3820,2550) 3820,2571.5 C3.1@3828.5,2580 ; C55.1@3878.5,4560 C54.1@3878.5,4630 3878.5,4638.5 v1(3898.3,4658.26) ; C57.1@3890,4388.5 3948.5,4388.5 v1@3955,4395 ; v1(3950,4400) 3988.5,4400 C56.1@4000,4388.5 ; TP4.1@3980,5430 JP11.1@3980,5360 4037,5360 4094.75,5302.25 D53.5@4130,5302.25 ; R6.2@4283.86,4539.17 4323.86,4539.17 ; D55.5@4509.02,4680 4436.18,4680 v1(4323.86,4567.68) 4323.86,4539.17 ; D10.5@4570.98,5050 v1(4610,5050) ; C87.1@4660.28,4544.62 4580.18,4544.62 U9.4@4574.27,4550.53 4559.27,4550.53 4536.27,4573.53 4399.2,4573.53 4364.84,4539.17 R5.2@4363.86,4539.17 4323.86,4539.17 ; R17.1@4778.5,2170 4778.5,2121.5 4845.51,2054.49 C6.2@4845.51,2004.65 4845.51,1963.15 v1(4848.5,1960.16) 4848.5,1896.14 C11.2@4850,1894.65 ; C7.1@4781.57,1818.51 C18.1@4781.57,1748.51 4781.57,1717.09 v1(4798.5,1700.16) 4782.52,1684.18 C8.1@4782.52,1644.65 ; R8.2@4948.5,2560 4950,2561.5 v1(4950,2620) 4950,2728.5 C25.1@4948.5,2730 4970,2730 4980.8,2740.8 4980.8,2940.7 4980,2941.5 R81.1@5040,3001.5 ; C69.2@5104.09,2228.74 5110.59,2222.24 v1(5150,2222.24) 5257.6,2222.24 C76.2@5264.09,2228.74 ; 2470,1553.03 2498.5,1524.53 C106.1@2498.5,1510 2506.14,1510 2566.14,1450 2630,1450 ; 2549.2,3959.2 2569.2,3959.2 v1@2570,3960 ; 2549.2,3959.2 2550,3960 v1@2570,3960 ; v1@2570,3960 v1@2580,3960 ; v1@2570,3960 v1(2580,3970) ; v1@2580,3960 v1(2580,3970)
3V3_LOAD: C187.1 C188.1 D56.4 D56.5 D56.6 LA8.5 R174.2 R212.2 TP35.1 U28.5 | length 1399.2
  Top Layer w10: v1(830,4995) 830,4840 v1(970,4700)
  Bottom Layer w10: LA8.5@516.14,4690.04 519.92,4693.82 523.27,4697.17 523.27,4722.76 ; D56.4@563.11,4762.6 D56.4@569.02,4762.6 ; TP35.1@597.32,4930 632.42,4894.9 ; C188.1@830,4942.57 C188.1@843.7,4928.87 ; v1(830,4995) 855.72,4969.28 868.03,4969.28 ; R174.2@910.12,4750 910.76,4749.36 910.76,4703.95 ; R212.2@910.76,4658.54 910.76,4703.95 ; 942.79,4980 955.63,4980 ; v1(970,4700) 966.05,4703.95 910.76,4703.95 ; 994,4946.92 997.86,4946.92 U28.5@1010,4934.78
  Bottom Layer w20: LA8.5@516.14,4690.04 517.8,4690.04 519.92,4692.17 519.92,4693.82 519.92,4719.41 523.27,4722.76 D56.4@563.11,4762.6 ; D56.4@569.02,4762.6 D56.5@569.02,4800 D56.6@569.02,4837.4 574.92,4837.4 632.42,4894.9 666.39,4928.87 C187.1@763.99,4928.87 843.7,4928.87 C188.1@843.99,4928.87 ; C188.1@853.68,4937.57 853.68,4954.93 861.87,4963.13 868.03,4969.28 882.38,4983.63 942.79,4983.63 955.63,4983.63 970,4983.63 994,4959.63 994,4946.92 994,4935.78 995,4934.78 U28.5@1010,4934.78
5V_AUX2: C99.1 C100.1 L42.2 L43.1 R120.1 | length 1596.4
  Top Layer w100: 500,3980 549.06,4029.06 L42.2@617.13,4029.06 ; 1300,3970 1318.07,3951.93 C100.1@1407.13,3951.93
  Bottom Layer w20: 1318.07,3951.93 1370,4003.86 R120.1@1370,4018.5
  Bottom Layer w100: 420,3570 470,3620 470,3950 480,3960 v2(510,3960) 1310,3960 1318.07,3951.93
  other v2: 1283.86,3940 1333.86,3940 470,3960 1283.86,3980 1333.86,3980 470,4000 510,4000
5V_COMP: Q12.3 Q23.4 Q23.6 R32.1 R34.1 | length 902.2
  Top Layer w10: v1(2920,3610) 2813.15,3716.85 v1(2813.15,3920) v1(2973.15,3920)
  Bottom Layer w10: v1(2813.15,3920) Q23.6@2862.6,3920 ; R34.1@2880,3608.5 2920,3608.5 R32.1@2960,3608.5 2989.01,3608.5 3015.13,3634.62 3050.07,3634.62 3065.9,3618.79 3065.9,3525.1 Q12.3@3070,3521 ; Q23.4@2937.4,3920 v1(2973.15,3920)
5V_ISO: C47.1 C48.1 C122.1 C185.1 D9.A D11.5 D58.4 D58.5 D58.6 JY5.2 JY6.2 L9.2 Q21.2 Q21.5 Q23.2 Q23.5 R9.2 R72.2 R75.1 R87.2 R88.2 TP16.1 U2.8 U28.1 | length 13045
  Top Layer w20: v1(1265.63,4980) 1401.13,4844.5 1843.29,4844.5 1904.5,4905.71 1904.5,4934.29 1890,4948.79 v1(1890,5011.5) ; v1(2973.15,3970) 3060,3970 ; v1(3120,4810) 3060,4750 3060,3970 ; L9.2@3170,3309.45 3190.55,3330 v1(3300,3330) ; TP16.1@3430,2788.5 3362.29,2788.5 U2.8@3357.29,2783.5 3357.29,3272.71 v1(3300,3330) ; v1(4610,4880) 4610,4950 4680,5020 4850,5020 JY6.2@4900,5070 ; 3060,3970 3320,3710 3320,3350 v1(3300,3330)
  Top Layer w100: v1(2459.45,3309.45) 2468.9,3300 v1(2630,3300) 3160.55,3300 L9.2@3170,3309.45
  Internal 2 w100: 1860.39,5019.61 1885.5,4994.5 1900.86,4994.5 2005.5,4889.86 2005.5,4859.14 2060,4804.64 2060,4350 2350,4060 2350,3598.98 2459.45,3489.54 v1(2459.45,3309.45)
  Bottom Layer w10: D11.5@610,1609.02 610,1589.35 621.82,1577.53 658,1577.53 672.99,1592.51 672.99,1664.9 689.98,1681.9 689.98,2559.98 850,2720 850,2981.92 887.58,3019.5 1822.22,3019.5 1823.14,3018.58 2283.44,3018.58 2454.85,3190 2520,3190 v1(2630,3300) ; Q23.5@2900,3920 2900,3983.15 ; Q23.2@2900,4026.3 2900,3983.15 ; R87.2@2951.5,4103.15 2980,4074.65 2980,4003.15 2960,3983.15 2900,3983.15
  Bottom Layer w20: U28.1@1117.98,4934.78 1208.81,4934.78 1219.65,4923.94 C122.1@1220.63,4923.94 1223.33,4926.63 1265.32,4926.63 ; v1(1265.63,4980) 1265.63,4926.94 1265.32,4926.63 ; C185.1@1310,4929.33 1307.3,4926.63 1265.32,4926.63 ; D58.4@1632.59,5124.82 D58.5@1669.99,5124.82 D58.6@1707.4,5124.82 1707.4,5097.81 1785.99,5019.22 v1(1832.19,5019.22) ; R9.2@1800.69,5154.78 1832.19,5123.28 Q21.2@1832.19,5067.93 v1(1832.19,5019.22) ; Q21.5@1832.19,4961.63 v1(1832.19,5019.22) ; v1(1890,5011.5) 1839.91,5011.5 v1(1832.19,5019.22) ; 2960,3983.15 v1(2973.15,3970) R75.1@3108.5,3970 ; v1(3120,4810) 3130,4820 3221.21,4820 3235.71,4805.5 3602.67,4805.5 3618.67,4821.5 3655.46,4821.5 3663.46,4813.5 3808,4813.5 R72.2@3860,4761.5 3986.35,4761.5 4010.35,4785.5 4180,4785.5 4274.5,4880 v1(4610,4880) ; D9.A@3190,3440 v1(3300,3330) 3308.51,3338.51 3338.51,3338.51 C47.1@3338.51,3268.51 R88.2@3338.51,3198.5
5V_MAIN: F4.2 L27.1 | length 143.7
  Top Layer w20: L27.1@1763.7,5172.68 1777.13,5186.1 L27.1@1777.13,5200 L27.1@1777.13,5207.13
  Top Layer w50: F4.2@1660,5172.68 L27.1@1763.7,5172.68
12V_AUX1: C91.1 C92.1 L39.2 L40.1 R112.1 | length 448.2
  Bottom Layer w20: v1(1600,3190) R112.1@1600,3228.5
  Bottom Layer w50: L40.1@383.46,3242.87 400,3226.34 v2@400,3160 ; v2@400,3110 v2(430,3110) v2(470,3110) v2(510,3110) v2(550,3110) ; 400,3140 v2@400,3160 ; v2(550,3160) v2(510,3160) v2(470,3160) v2(430,3160) v2@400,3160
  other v2: 390,3110 390,3160
12V_AVAIL: C4.1 Q39.4 Q39.6 R145.2 U1.16 | length 541.7
  Top Layer w10: U1.16@3595.83,2590.43 3597.72,2588.54 3624.69,2588.54 3633.24,2580 v1(3640,2580)
  Bottom Layer w10: Q39.4@3343.55,2368.58 3350.36,2375.39 3350.36,2404.1 3355.31,2409.06 3418.35,2409.06 ; Q39.6@3418.35,2368.58 3418.35,2409.06 ; C4.1@3581.5,2580 3567.8,2566.3 3567.8,2538.3 3484.93,2455.43 R145.2@3412.44,2455.43 3418.35,2449.53 3418.35,2409.06
  Bottom Layer w20: C4.1@3581.5,2580 v1(3640,2580)
12V_ISO: C23.1 C45.1 C46.1 D46.A D51.1 D51.2 JY6.4 L6.2 Q8.2 Q8.5 Q13.2 Q13.5 Q39.2 Q39.5 R4.2 R40.2 R42.1 R142.2 TP17.1 U2.2 U2.7 | length 13534
  Top Layer w10: D51.2@2815.2,1689.37 D51.1@2890,1689.37 3226.89,1689.37 L6.2@3290.55,1753.03
  Top Layer w20: D46.A@2545.35,1820 2690,1820 2870,2000 2890,2000 ; v1(2650,4800) v1(2890,5040) ; 2921.5,2530 2951.5,2560 3390,2560 3448.5,2618.5 3448.5,2701.01 3416.01,2733.5 U2.7@3357.29,2733.5
  Top Layer w30: 2918.52,2478.52 2945.75,2505.75 ; TP17.1@3010,2718.5 3025,2733.5 v1(3083.86,2733.5) U2.2@3142.72,2733.5
  Top Layer w75: v1@3367.52,1830 3695.14,1830 ; 3697.23,1827.91 4065.98,1827.91
  Top Layer w80: 4065.98,1827.91 C23.1@4150,1911.93
  Top Layer w100: v1(2450,2890) 2507.05,2890 2867.05,2530 ; TP17.1@3010,2718.5 2921.5,2630 2921.5,2530 2867.05,2530 ; v1@3367.52,1830 L6.2@3290.55,1753.03 3136.97,1753.03 2890,2000 2890,2507.05 2867.05,2530
  Internal 2 w15: 3036.75,5436.75 4053.25,5436.75
  Internal 2 w20: v1(2890,5040) 2910,5060 2910,5310 3036.75,5436.75 ; 4053.25,5436.75 4119,5371 4269,5371 4480,5160 4950,5160 4980,5130 4980,5050 JY6.4@4900,4970
  Internal 2 w100: v1@941.7,5370 951.7,5370 1091.7,5370 1241.7,5220 1439,5220 1599,5060 1599,4972.61 1776.61,4795 v1(1795,4795) 1940,4650 1940,4235.36 2218.5,3956.86 2218.5,3851.5 2230,3840 2230,3580 2200,3550 2200,3535.36 2170,3505.36 2170,3354.64 2189.5,3335.14 2189.5,3248.79 2175.5,3234.79 2175.5,3164.5 2438,2902 v1@2450,2902
  Bottom Layer w10: v1(4100,1860) 4120,1880 R42.1@4120,2107.01
  Bottom Layer w20: Q8.5@888.55,5360 v1(941.7,5360) ; v1(941.7,5400) v1(941.7,5360) ; Q8.2@994.85,5360 v1(941.7,5360) ; R4.2@1061.7,5361.5 1091.7,5391.5 v1(1091.7,5400) ; v1@1255.63,5223.15 Q13.2@1255.63,5270 Q13.5@1255.63,5376.3 ; R40.2@1287.13,5173.15 1255.63,5204.65 1255.63,5213.15 v1(1265.63,5223.15) v1(1305.63,5223.15) ; v1(1795,4795) 1853.12,4736.88 2586.88,4736.88 v1(2650,4800) ; v1@3370,1847.8 3458.3,1936.11 3458.3,2128.59 3412.44,2174.45 R142.2@3412.44,2175.43 3412.44,2176.42 3454.24,2218.21 3454.24,2283.9 3437.2,2300.94 3399.5,2300.94 3382.76,2284.2 3382.76,2264.09 Q39.2@3380.95,2262.28 Q39.5@3380.95,2368.58
  Bottom Layer w30: C46.1@3040,2727.01 3046.5,2733.5 v1(3083.86,2733.5) 3123.5,2733.5 C45.1@3130,2727.01
  other v1: 3370,1845.76
12V_MAIN: F3.2 L28.2 | length 102.4
  Top Layer w20: F3.2@1683.03,5350 F3.2@1689.61,5356.57 ; 1750,5360 1767.13,5360 L28.2@1777.13,5370
  Top Layer w100: F3.2@1689.61,5356.57 1746.57,5356.57 1750,5360
24V: D44.A1 D44.A2 L47.1 Q20.7 Q20.8 R80.2 | length 4238.1
  Top Layer w20: Q20.7@785,245 v2(810,220) 913,117 v1@1047,117 ; R80.2@3481.5,1530 3485.28,1533.78 D44.A2@3560,1533.78 D44.A2@3563.31,1533.78 ; v1(3510,1470) 3563.31,1523.31 D44.A2@3563.31,1533.78 ; D44.A1@3563.31,1606.22 D44.A2@3563.31,1533.78
  Top Layer w30: Q20.7@752.4,245 Q20.7@785,245
  Top Layer w60: L47.1@602.87,310 602.87,279.25 609.45,272.68 640.2,272.68 692.87,220 752.4,220 772.34,220
  Internal 2 w20: v1(1050,130) 1070,150 1070,440 1070,442.13 ; 1070,450 1184,564 1205.82,564 1299.82,658 1488.85,658 1786.85,956 2049.84,956 2053.84,960 2850,960 2850,964.15 3225.35,1339.5 ; v1(3510,1470) 3360,1470 ; 3225.35,1339.5 3229.5,1339.5 3360,1470 ; 3225.35,1339.5 3355.85,1470 3360,1470
  Bottom Layer w40: v2(810,220) v2(860,220)
COMP.EN: JY8.2 NT6.1 Q9.1 R31.1 | length 696.9
  Top Layer w10: NT6.1@2789.68,4400 2810,4400 2860,4350 2860,4230 2830,4200 v1(2830,4091.5)
  Bottom Layer w10: Q9.1@2682.6,3819 2740,3876.4 2740,3943.15 2738.31,3944.83 2738.31,3999.81 R31.1@2770,4031.5 v1(2830,4091.5)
